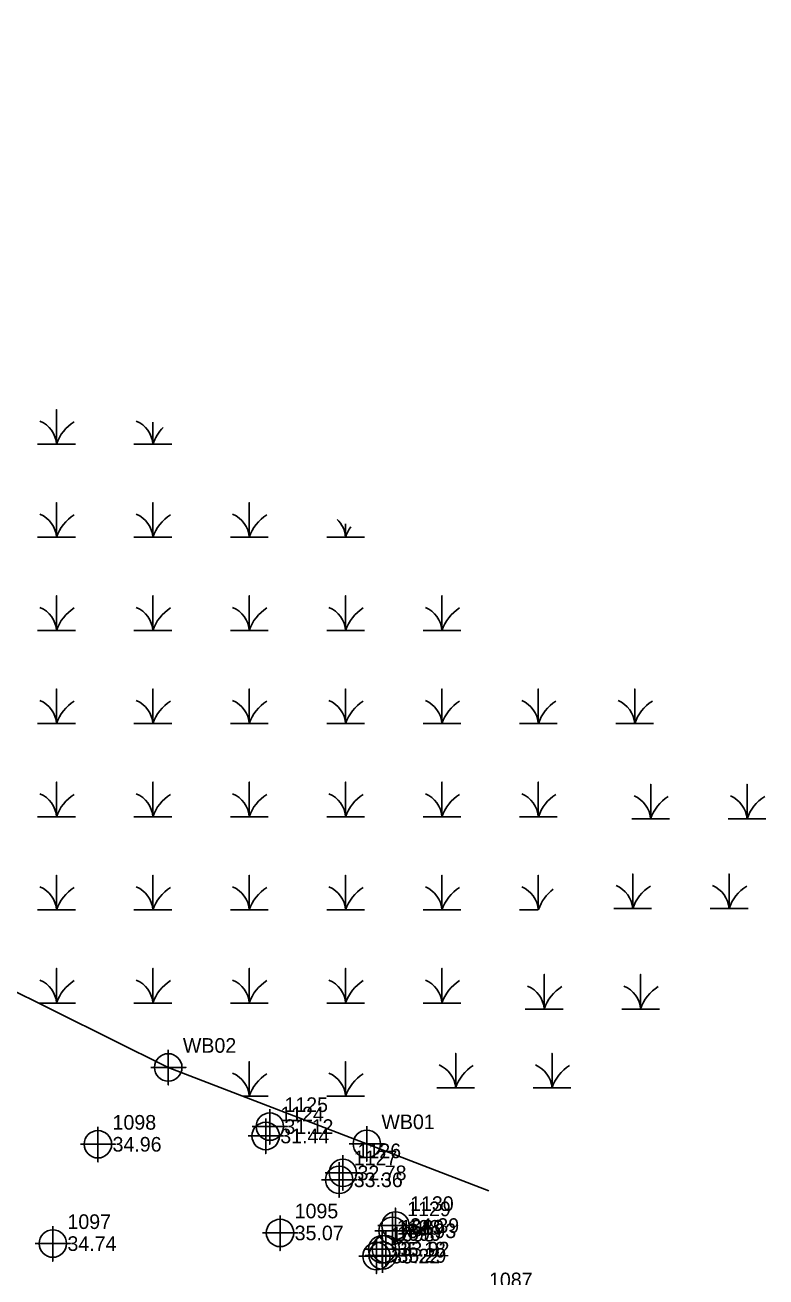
# Model space of a CAD drawing. Extents: x 2138832 to 2141061, y 149156 to 150675.
# Drawn here: x 2140515.2 to 2140641.7, y 149449.6 to 149663.5 of the extents above; entities that cross this region are included whole.
import ezdxf

# ---------------------------------------------------------------- set-up
doc = ezdxf.new("R2010")
doc.units = 0
for name, color, linetype in [('Exist Environmental Wetland Boundary', 7, 'Continuous'), ('Exist Environmental Wetland Boundary Cogo Number', 7, 'Continuous'), ('Exist Environmental Wetland Boundary Cogo Point CELL', 7, 'Continuous'), ('Exist Roads EOP Cogo Elevation', 7, 'Continuous'), ('Exist Roads EOP Cogo Number', 7, 'Continuous'), ('Exist Roads EOP Cogo Point CELL', 7, 'Continuous'), ('Exist Structure Major Bridge Seam Cogo Number', 7, 'Continuous'), ('Exist Structure Major Bridge Seat Cogo Elevation', 7, 'Continuous'), ('Exist Structure Major Bridge Seat Cogo Number', 7, 'Continuous'), ('Exist Structure Major Bridge Seat Cogo Point CELL', 7, 'Continuous'), ('Exist Structure Major Bridge WW Cogo Elevation', 7, 'Continuous'), ('Exist Structure Major Bridge WW Cogo Number', 7, 'Continuous'), ('Exist Structure Major Bridge WW Cogo Point CELL', 7, 'Continuous'), ('Exist Structure Major Deck Tunnel Box Culvert Cogo Elevation', 7, 'Continuous'), ('Exist Structure Major Deck Tunnel Box Culvert Cogo Number', 7, 'Continuous'), ('Exist Structure Major Deck Tunnel Box Culvert Cogo Point CELL', 7, 'Continuous'), ('Exist Utilities Telephone UG FO SUE LOS C Cogo Elevation', 7, 'Continuous'), ('Exist Utilities Telephone UG FO SUE LOS C Cogo Number', 7, 'Continuous'), ('Exist Utilities Telephone UG FO SUE LOS C Cogo Point CELL', 7, 'Continuous')]:
    doc.layers.add(name, color=color, linetype=linetype)

msp = doc.modelspace()

# ---------------------------------------------------------------- linework, layer by layer
at = {"layer": 'Exist Environmental Wetland Boundary'}
msp.add_lwpolyline([(2140220.74, 149663.51), (2140255.42, 149635.3), (2140277.39, 149631.77), (2140314.58, 149625.36), (2140349.86, 149614.36), (2140381.04, 149593.89), (2140416.32, 149561.58), (2140450.05, 149576.57), (2140474.9, 149577.61), (2140477.45, 149542.55), (2140488.03, 149517.58), (2140501.09, 149504.55), (2140539.61, 149485.41), (2140594.36, 149464.34)], dxfattribs=at)
at = {"layer": 'Exist Environmental Wetland Boundary Cogo Point CELL'}
msp.add_line((2140599.57, 149512.32), (2140602.76, 149512.32), dxfattribs=at)
for points in [[(2140517.31, 149591.91), (2140520.54, 149591.91), (2140520.54, 149597.82), (2140520.54, 149591.91), (2140523.76, 149591.91)], [(2140533.76, 149591.91), (2140536.99, 149591.91), (2140536.99, 149595.68)], [(2140536.99, 149595.68), (2140536.99, 149591.91), (2140540.22, 149591.91)], [(2140517.31, 149575.99), (2140520.54, 149575.99), (2140520.54, 149581.91), (2140520.54, 149575.99), (2140523.76, 149575.99)], [(2140533.76, 149575.99), (2140536.99, 149575.99), (2140536.99, 149581.91), (2140536.99, 149575.99), (2140540.22, 149575.99)], [(2140550.22, 149575.99), (2140553.44, 149575.99), (2140553.44, 149581.91), (2140553.44, 149575.99), (2140556.67, 149575.99)], [(2140566.67, 149575.99), (2140569.89, 149575.99), (2140569.89, 149578.26)], [(2140569.89, 149578.26), (2140569.89, 149575.99), (2140573.12, 149575.99)], [(2140517.31, 149560.07), (2140520.54, 149560.07), (2140520.54, 149565.99), (2140520.54, 149560.07), (2140523.76, 149560.07)], [(2140533.76, 149560.07), (2140536.99, 149560.07), (2140536.99, 149565.99), (2140536.99, 149560.07), (2140540.22, 149560.07)], [(2140550.22, 149560.07), (2140553.44, 149560.07), (2140553.44, 149565.99), (2140553.44, 149560.07), (2140556.67, 149560.07)], [(2140566.67, 149560.07), (2140569.89, 149560.07), (2140569.89, 149565.99), (2140569.89, 149560.07), (2140573.12, 149560.07)], [(2140583.12, 149560.07), (2140586.34, 149560.07), (2140586.34, 149565.99), (2140586.34, 149560.07), (2140589.57, 149560.07)], [(2140517.31, 149544.15), (2140520.54, 149544.15), (2140520.54, 149550.07), (2140520.54, 149544.15), (2140523.76, 149544.15)], [(2140533.76, 149544.15), (2140536.99, 149544.15), (2140536.99, 149550.07), (2140536.99, 149544.15), (2140540.22, 149544.15)], [(2140550.22, 149544.15), (2140553.44, 149544.15), (2140553.44, 149550.07), (2140553.44, 149544.15), (2140556.67, 149544.15)], [(2140566.67, 149544.15), (2140569.89, 149544.15), (2140569.89, 149550.07), (2140569.89, 149544.15), (2140573.12, 149544.15)], [(2140583.12, 149544.15), (2140586.34, 149544.15), (2140586.34, 149550.07), (2140586.34, 149544.15), (2140589.57, 149544.15)], [(2140599.57, 149544.15), (2140602.79, 149544.15), (2140602.79, 149550.07), (2140602.79, 149544.15), (2140606.02, 149544.15)], [(2140616.02, 149544.15), (2140619.25, 149544.15), (2140619.25, 149550.07), (2140619.25, 149544.15), (2140622.47, 149544.15)], [(2140517.31, 149528.24), (2140520.54, 149528.24), (2140520.54, 149534.15), (2140520.54, 149528.24), (2140523.76, 149528.24)], [(2140533.76, 149528.24), (2140536.99, 149528.24), (2140536.99, 149534.15), (2140536.99, 149528.24), (2140540.22, 149528.24)], [(2140550.22, 149528.24), (2140553.44, 149528.24), (2140553.44, 149534.15), (2140553.44, 149528.24), (2140556.67, 149528.24)], [(2140566.67, 149528.24), (2140569.89, 149528.24), (2140569.89, 149534.15), (2140569.89, 149528.24), (2140573.12, 149528.24)], [(2140583.12, 149528.24), (2140586.34, 149528.24), (2140586.34, 149534.15), (2140586.34, 149528.24), (2140589.57, 149528.24)], [(2140599.57, 149528.24), (2140602.79, 149528.24), (2140602.79, 149534.15), (2140602.79, 149528.24), (2140606.02, 149528.24)], [(2140618.75, 149527.87), (2140621.97, 149527.87), (2140621.97, 149533.78), (2140621.97, 149527.87), (2140625.2, 149527.87)], [(2140635.2, 149527.87), (2140638.42, 149527.87), (2140638.42, 149533.78), (2140638.42, 149527.87), (2140641.65, 149527.87)], [(2140517.31, 149512.32), (2140520.54, 149512.32), (2140520.54, 149518.24), (2140520.54, 149512.32), (2140523.76, 149512.32)], [(2140533.76, 149512.32), (2140536.99, 149512.32), (2140536.99, 149518.24), (2140536.99, 149512.32), (2140540.22, 149512.32)], [(2140550.22, 149512.32), (2140553.44, 149512.32), (2140553.44, 149518.24), (2140553.44, 149512.32), (2140556.67, 149512.32)], [(2140566.67, 149512.32), (2140569.89, 149512.32), (2140569.89, 149518.24), (2140569.89, 149512.32), (2140573.12, 149512.32)], [(2140583.12, 149512.32), (2140586.34, 149512.32), (2140586.34, 149518.24), (2140586.34, 149512.32), (2140589.57, 149512.32)], [(2140602.79, 149512.36), (2140602.79, 149518.24), (2140602.79, 149512.36)], [(2140615.68, 149512.54), (2140618.91, 149512.54), (2140618.91, 149518.46), (2140618.91, 149512.54), (2140622.14, 149512.54)], [(2140632.14, 149512.54), (2140635.36, 149512.54), (2140635.36, 149518.46), (2140635.36, 149512.54), (2140638.59, 149512.54)], [(2140517.48, 149496.4), (2140520.54, 149496.4), (2140520.54, 149502.32), (2140520.54, 149496.4), (2140523.76, 149496.4)], [(2140533.76, 149496.4), (2140536.99, 149496.4), (2140536.99, 149502.32), (2140536.99, 149496.4), (2140540.22, 149496.4)], [(2140550.22, 149496.4), (2140553.44, 149496.4), (2140553.44, 149502.32), (2140553.44, 149496.4), (2140556.67, 149496.4)], [(2140566.67, 149496.4), (2140569.89, 149496.4), (2140569.89, 149502.32), (2140569.89, 149496.4), (2140573.12, 149496.4)], [(2140583.12, 149496.4), (2140586.34, 149496.4), (2140586.34, 149502.32), (2140586.34, 149496.4), (2140589.57, 149496.4)], [(2140600.57, 149495.38), (2140603.8, 149495.38), (2140603.8, 149501.3), (2140603.8, 149495.38), (2140607.02, 149495.38)], [(2140617.02, 149495.38), (2140620.25, 149495.38), (2140620.25, 149501.3), (2140620.25, 149495.38), (2140623.47, 149495.38)], [(2140539.61, 149488.41), (2140539.61, 149482.41), (2140539.61, 149485.41), (2140542.61, 149485.41), (2140536.61, 149485.41)], [(2140552.4, 149480.48), (2140553.44, 149480.48), (2140553.44, 149486.4), (2140553.44, 149480.48), (2140556.67, 149480.48)], [(2140566.67, 149480.48), (2140569.89, 149480.48), (2140569.89, 149486.4), (2140569.89, 149480.48), (2140573.12, 149480.48)], [(2140585.46, 149481.89), (2140588.68, 149481.89), (2140588.68, 149487.81), (2140588.68, 149481.89), (2140591.91, 149481.89)], [(2140601.91, 149481.89), (2140605.13, 149481.89), (2140605.13, 149487.81), (2140605.13, 149481.89), (2140608.36, 149481.89)], [(2140573.5, 149475.36), (2140573.5, 149469.36), (2140573.5, 149472.36), (2140576.5, 149472.36), (2140570.5, 149472.36)]]:
    msp.add_lwpolyline(points, dxfattribs=at)
for centre in [(2140539.61, 149485.41), (2140573.5, 149472.36)]:
    msp.add_circle(centre, 2.34, dxfattribs=at)
for centre, radius, start, end in [((2140515.94, 149591.57), 4.61, 4.1403, 67.535), ((2140527.38, 149589.63), 7.21, 122.1274, 161.6222), ((2140532.39, 149591.57), 4.61, 4.1403, 67.535), ((2140543.83, 149589.63), 7.21, 134.7986, 161.6222), ((2140515.94, 149575.66), 4.61, 4.1403, 67.535), ((2140527.38, 149573.72), 7.21, 122.1274, 161.6222), ((2140532.39, 149575.66), 4.61, 4.1403, 67.535), ((2140543.83, 149573.72), 7.21, 122.1274, 161.6222), ((2140548.84, 149575.66), 4.61, 4.1403, 67.535), ((2140560.28, 149573.72), 7.21, 122.1274, 161.6222), ((2140565.29, 149575.66), 4.61, 4.1403, 47.061), ((2140576.73, 149573.72), 7.21, 145.6105, 161.6222), ((2140515.94, 149559.74), 4.61, 4.1403, 67.535), ((2140527.38, 149557.8), 7.21, 122.1274, 161.6222), ((2140532.39, 149559.74), 4.61, 4.1403, 67.535), ((2140543.83, 149557.8), 7.21, 122.1274, 161.6222), ((2140548.84, 149559.74), 4.61, 4.1403, 67.535), ((2140560.28, 149557.8), 7.21, 122.1274, 161.6222), ((2140565.29, 149559.74), 4.61, 4.1403, 67.535), ((2140576.73, 149557.8), 7.21, 122.1274, 161.6222), ((2140581.74, 149559.74), 4.61, 4.1403, 67.535), ((2140593.18, 149557.8), 7.21, 122.1274, 161.6222), ((2140515.94, 149543.82), 4.61, 4.1403, 67.535), ((2140527.38, 149541.88), 7.21, 122.1274, 161.6222), ((2140532.39, 149543.82), 4.61, 4.1403, 67.535), ((2140543.83, 149541.88), 7.21, 122.1274, 161.6222), ((2140548.84, 149543.82), 4.61, 4.1403, 67.535), ((2140560.28, 149541.88), 7.21, 122.1274, 161.6222), ((2140565.29, 149543.82), 4.61, 4.1403, 67.535), ((2140576.73, 149541.88), 7.21, 122.1274, 161.6222), ((2140581.74, 149543.82), 4.61, 4.1403, 67.535), ((2140593.18, 149541.88), 7.21, 122.1274, 161.6222), ((2140598.19, 149543.82), 4.61, 4.1403, 67.535), ((2140609.64, 149541.88), 7.21, 122.1274, 161.6222), ((2140614.65, 149543.82), 4.61, 4.1403, 67.535), ((2140626.09, 149541.88), 7.21, 122.1274, 161.6222), ((2140515.94, 149527.9), 4.61, 4.1403, 67.535), ((2140527.38, 149525.96), 7.21, 122.1274, 161.6222), ((2140532.39, 149527.9), 4.61, 4.1403, 67.535), ((2140543.83, 149525.96), 7.21, 122.1274, 161.6222), ((2140548.84, 149527.9), 4.61, 4.1403, 67.535), ((2140560.28, 149525.96), 7.21, 122.1274, 161.6222), ((2140565.29, 149527.9), 4.61, 4.1403, 67.535), ((2140576.73, 149525.96), 7.21, 122.1274, 161.6222), ((2140581.74, 149527.9), 4.61, 4.1403, 67.535), ((2140593.18, 149525.96), 7.21, 122.1274, 161.6222), ((2140598.19, 149527.9), 4.61, 4.1403, 67.535), ((2140609.64, 149525.96), 7.21, 122.1274, 161.6222), ((2140617.37, 149527.53), 4.61, 4.1403, 67.535), ((2140628.81, 149525.59), 7.21, 122.1274, 161.6222), ((2140633.82, 149527.53), 4.61, 4.1403, 67.535), ((2140645.27, 149525.59), 7.21, 122.1274, 161.6222), ((2140614.31, 149512.21), 4.61, 4.1403, 67.535), ((2140625.75, 149510.27), 7.21, 122.1274, 161.6222), ((2140630.76, 149512.21), 4.61, 4.1403, 67.535), ((2140642.2, 149510.27), 7.21, 122.1274, 161.6222), ((2140515.94, 149511.99), 4.61, 4.1403, 67.535), ((2140527.38, 149510.05), 7.21, 122.1274, 161.6222), ((2140532.39, 149511.99), 4.61, 4.1403, 67.535), ((2140543.83, 149510.05), 7.21, 122.1274, 161.6222), ((2140548.84, 149511.99), 4.61, 4.1403, 67.535), ((2140560.28, 149510.05), 7.21, 122.1274, 161.6222), ((2140565.29, 149511.99), 4.61, 4.1403, 67.535), ((2140576.73, 149510.05), 7.21, 122.1274, 161.6222), ((2140581.74, 149511.99), 4.61, 4.1403, 67.535), ((2140593.18, 149510.05), 7.21, 122.1274, 161.6222), ((2140598.19, 149511.99), 4.61, 4.6178, 67.535), ((2140609.64, 149510.05), 7.21, 126.6073, 160.9614), ((2140515.94, 149496.07), 4.61, 4.1403, 67.535), ((2140527.38, 149494.13), 7.21, 122.1274, 161.6222), ((2140532.39, 149496.07), 4.61, 4.1403, 67.535), ((2140543.83, 149494.13), 7.21, 122.1274, 161.6222), ((2140548.84, 149496.07), 4.61, 4.1403, 67.535), ((2140560.28, 149494.13), 7.21, 122.1274, 161.6222), ((2140565.29, 149496.07), 4.61, 4.1403, 67.535), ((2140576.73, 149494.13), 7.21, 122.1274, 161.6222), ((2140581.74, 149496.07), 4.61, 4.1403, 67.535), ((2140593.18, 149494.13), 7.21, 122.1274, 161.6222), ((2140599.2, 149495.05), 4.61, 4.1403, 67.535), ((2140615.65, 149495.05), 4.61, 4.1403, 67.535), ((2140610.64, 149493.11), 7.21, 122.1274, 161.6222), ((2140627.09, 149493.11), 7.21, 122.1274, 161.6222), ((2140548.84, 149480.15), 4.61, 4.1403, 67.535), ((2140560.28, 149478.21), 7.21, 122.1274, 161.6222), ((2140565.29, 149480.15), 4.61, 4.1403, 67.535), ((2140576.73, 149478.21), 7.21, 122.1274, 161.6222), ((2140584.08, 149481.56), 4.61, 4.1403, 67.535), ((2140595.52, 149479.62), 7.21, 122.1274, 161.6222), ((2140600.53, 149481.56), 4.61, 4.1403, 67.535), ((2140611.97, 149479.62), 7.21, 122.1274, 161.6222)]:
    msp.add_arc(centre, radius, start, end, dxfattribs=at)
at = {"layer": 'Exist Roads EOP Cogo Point CELL'}
for points in [[(2140527.6, 149475.27), (2140527.6, 149469.27), (2140527.6, 149472.27), (2140530.6, 149472.27), (2140524.6, 149472.27)], [(2140558.69, 149460.12), (2140558.69, 149454.12), (2140558.69, 149457.12), (2140561.69, 149457.12), (2140555.69, 149457.12)], [(2140519.9, 149458.3), (2140519.9, 149452.3), (2140519.9, 149455.3), (2140522.9, 149455.3), (2140516.9, 149455.3)], [(2140575.15, 149456.17), (2140575.15, 149450.17), (2140575.15, 149453.17), (2140578.15, 149453.17), (2140572.15, 149453.17)]]:
    msp.add_lwpolyline(points, dxfattribs=at)
for centre in [(2140527.6, 149472.27), (2140558.69, 149457.12), (2140519.9, 149455.3), (2140575.15, 149453.17)]:
    msp.add_circle(centre, 2.34, dxfattribs=at)
at = {"layer": 'Exist Structure Major Bridge Seat Cogo Point CELL'}
msp.add_lwpolyline([(2140573.75, 149454.36), (2140579.75, 149454.36), (2140576.75, 149454.36), (2140576.75, 149457.36), (2140576.75, 149451.36)], dxfattribs=at)
msp.add_circle((2140576.75, 149454.36), 2.34, dxfattribs=at)
at = {"layer": 'Exist Structure Major Bridge WW Cogo Point CELL'}
for points in [[(2140575.4, 149458.38), (2140581.4, 149458.38), (2140578.4, 149458.38), (2140578.4, 149461.38), (2140578.4, 149455.38)], [(2140574.9, 149457.49), (2140580.9, 149457.49), (2140577.9, 149457.49), (2140577.9, 149460.49), (2140577.9, 149454.49)], [(2140573.12, 149454.33), (2140579.12, 149454.33), (2140576.12, 149454.33), (2140576.12, 149457.33), (2140576.12, 149451.33)]]:
    msp.add_lwpolyline(points, dxfattribs=at)
for centre in [(2140577.9, 149457.49), (2140578.4, 149458.38), (2140576.12, 149454.33)]:
    msp.add_circle(centre, 2.34, dxfattribs=at)
at = {"layer": 'Exist Structure Major Deck Tunnel Box Culvert Cogo Point CELL'}
msp.add_lwpolyline([(2140573.21, 149453.28), (2140579.21, 149453.28), (2140576.21, 149453.28), (2140576.21, 149456.28), (2140576.21, 149450.28)], dxfattribs=at)
msp.add_circle((2140576.21, 149453.28), 2.34, dxfattribs=at)
at = {"layer": 'Exist Utilities Telephone UG FO SUE LOS C Cogo Point CELL'}
for points in [[(2140556.94, 149478.29), (2140556.94, 149472.29), (2140556.94, 149475.29), (2140559.94, 149475.29), (2140553.94, 149475.29)], [(2140556.24, 149476.69), (2140556.24, 149470.69), (2140556.24, 149473.69), (2140559.24, 149473.69), (2140553.24, 149473.69)], [(2140569.42, 149470.39), (2140569.42, 149464.39), (2140569.42, 149467.39), (2140572.42, 149467.39), (2140566.42, 149467.39)], [(2140568.78, 149469.2), (2140568.78, 149463.2), (2140568.78, 149466.2), (2140571.78, 149466.2), (2140565.78, 149466.2)]]:
    msp.add_lwpolyline(points, dxfattribs=at)
for centre in [(2140556.24, 149473.69), (2140556.94, 149475.29), (2140569.42, 149467.39), (2140568.78, 149466.2)]:
    msp.add_circle(centre, 2.34, dxfattribs=at)

# ---------------------------------------------------------------- texts
at = {"layer": 'Exist Environmental Wetland Boundary Cogo Number'}
for s, p in [('WB02', (2140542.11, 149487.91)), ('WB01', (2140576, 149474.86))]:
    msp.add_text(s, height=2.5, dxfattribs=at).set_placement(p)
at = {"layer": 'Exist Roads EOP Cogo Elevation'}
for s, p in [('34.96', (2140530.1, 149471.02)), ('34.74', (2140522.4, 149454.05)), ('35.07', (2140561.19, 149455.87)), ('35.22', (2140577.65, 149451.92))]:
    msp.add_text(s, height=2.5, dxfattribs=at).set_placement(p)
at = {"layer": 'Exist Roads EOP Cogo Number'}
for s, p in [('1098', (2140530.1, 149474.77)), ('1095', (2140561.19, 149459.62)), ('1097', (2140522.4, 149457.8)), ('1093', (2140577.65, 149455.67))]:
    msp.add_text(s, height=2.5, dxfattribs=at).set_placement(p)
at = {"layer": 'Exist Structure Major Bridge Seam Cogo Number'}
msp.add_text('1087', height=2.5, dxfattribs=at).set_placement((2140594.37, 149447.84))
at = {"layer": 'Exist Structure Major Bridge Seat Cogo Elevation'}
msp.add_text('33.92', height=2.5, dxfattribs=at).set_placement((2140579.25, 149453.11))
at = {"layer": 'Exist Structure Major Bridge Seat Cogo Number'}
msp.add_text('1089', height=2.5, dxfattribs=at).set_placement((2140579.25, 149456.86))
at = {"layer": 'Exist Structure Major Bridge WW Cogo Elevation'}
for s, p in [('34.93', (2140580.4, 149456.24)), ('34.39', (2140580.9, 149457.13)), ('35.18', (2140578.62, 149453.08))]:
    msp.add_text(s, height=2.5, dxfattribs=at).set_placement(p)
at = {"layer": 'Exist Structure Major Bridge WW Cogo Number'}
for s, p in [('1130', (2140580.9, 149460.88)), ('1129', (2140580.4, 149459.99)), ('1128', (2140578.62, 149456.83))]:
    msp.add_text(s, height=2.5, dxfattribs=at).set_placement(p)
at = {"layer": 'Exist Structure Major Deck Tunnel Box Culvert Cogo Elevation'}
msp.add_text('35.29', height=2.5, dxfattribs=at).set_placement((2140578.71, 149452.03))
at = {"layer": 'Exist Structure Major Deck Tunnel Box Culvert Cogo Number'}
msp.add_text('1090', height=2.5, dxfattribs=at).set_placement((2140578.71, 149455.78))
at = {"layer": 'Exist Utilities Telephone UG FO SUE LOS C Cogo Elevation'}
for s, p in [('31.12', (2140559.44, 149474.04)), ('31.44', (2140558.74, 149472.44)), ('33.36', (2140571.28, 149464.95)), ('32.78', (2140571.92, 149466.14))]:
    msp.add_text(s, height=2.5, dxfattribs=at).set_placement(p)
at = {"layer": 'Exist Utilities Telephone UG FO SUE LOS C Cogo Number'}
for s, p in [('1125', (2140559.44, 149477.79)), ('1124', (2140558.74, 149476.19)), ('1126', (2140571.92, 149469.89)), ('1127', (2140571.28, 149468.7))]:
    msp.add_text(s, height=2.5, dxfattribs=at).set_placement(p)

doc.saveas('drawing.dxf')
